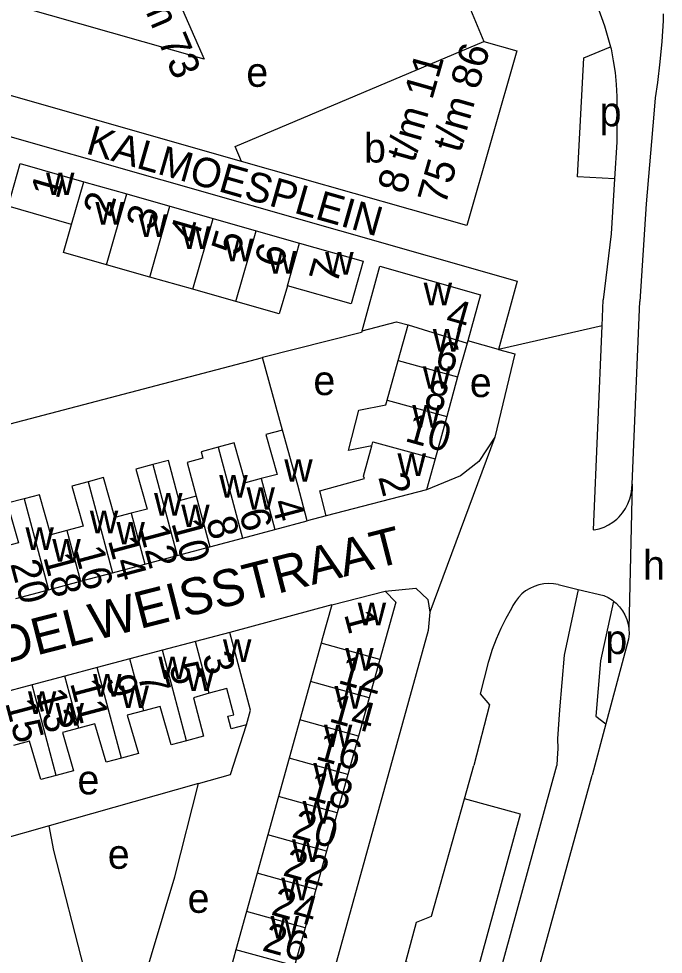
# Model space of a CAD drawing. Extents: x 161258 to 163262, y 380749 to 382054.
# Drawn here: x 163054.8 to 163142.3, y 381090.7 to 381217.9 of the extents above; entities that cross this region are included whole.
import ezdxf

# ---------------------------------------------------------------- set-up
doc = ezdxf.new("R2010")
doc.units = 0
for name, color, linetype in [('BLT_Basislijn', 7, 'Continuous'), ('BLT_Bebouwing', 7, 'Continuous'), ('BLT_Centroide', 7, 'Continuous'), ('BLT_Huisnummer', 7, 'Continuous'), ('BLT_Huisnummer_ tussenligend', 7, 'Continuous'), ('BLT_Huisnummer_reeks', 7, 'Continuous'), ('BLT_Onderverdeling_panden', 7, 'Continuous'), ('BLT_Straatnaam', 7, 'Continuous'), ('BLT_Straatnaam_verkleind', 7, 'Continuous'), ('BLT_Vlakafsluiter', 7, 'Continuous')]:
    doc.layers.add(name, color=color, linetype=linetype)

msp = doc.modelspace()

# ---------------------------------------------------------------- linework, layer by layer
at = {"layer": 'BLT_Basislijn'}
for p, q in [((163113.62, 381225.09), (163117.96, 381214.78)), ((163141.24, 381207.1), (163141.05, 381204.87)), ((163136, 381205.08), (163136.04, 381201.07)), ((163141.05, 381204.87), (163140, 381192.69)), ((163136.04, 381201.07), (163135.71, 381196.09)), ((163140, 381192.69), (163139.16, 381179.42)), ((163134.02, 381176.13), (163134.17, 381179.63)), ((163138.1, 381154.57), (163139.16, 381179.42)), ((163132.84, 381148.39), (163134.02, 381176.13)), ((163090.58, 381161.94), (163087.88, 381171.79)), ((163096.54, 381150.3), (163093.96, 381149.62)), ((163128.07, 381140.95), (163130.78, 381140.29)), ((163130.78, 381140.29), (163134.26, 381139.44)), ((163097.29, 381138.17), (163083.45, 381134.41)), ((163137.62, 381133.52), (163134.54, 381122.01)), ((163133.17, 381123.03), (163134.54, 381122.01)), ((163134.54, 381122.01), (163132.67, 381115.03)), ((163114.72, 381068.34), (163127.85, 381116.36)), ((163120.56, 381071.17), (163132.67, 381115.03)), ((163079.2, 381113.89), (163058.89, 381108.13)), ((163058.89, 381108.13), (163047.26, 381104.82))]:
    msp.add_line(p, q, dxfattribs=at)
for points in [[(163131.18, 381225.72), (163134.36, 381216.92), (163135.16, 381214.06)], [(163142.33, 381218.55), (163142.3, 381217.57), (163142.13, 381214.78), (163141.88, 381211.99), (163141.55, 381209.21), (163141.24, 381207.1)], [(163135.71, 381196.09), (163130.69, 381196.39), (163131.52, 381212.56), (163135.16, 381214.06)], [(163135.16, 381214.06), (163135.23, 381213.77), (163135.54, 381212.16), (163135.78, 381210.54), (163135.94, 381208.91), (163136.02, 381207.28), (163136.02, 381205.64), (163136, 381205.08)], [(163085.04, 381198.47), (163051.49, 381208.03)], [(163050.01, 381202.84), (163122.5, 381182.17), (163119.93, 381172.92)], [(163135.71, 381196.09), (163135.23, 381188.62), (163134.17, 381179.63)], [(163101.42, 381175.42), (163101.34, 381175.22), (163087.88, 381171.79)], [(163119.93, 381172.92), (163115.77, 381174.09)], [(163119.93, 381172.92), (163122.14, 381172.29), (163119.45, 381161)], [(163030.95, 381156.84), (163087.04, 381171.57), (163087.88, 381171.79)], [(163119.45, 381161), (163117.26, 381157.68), (163114.77, 381155.73), (163110.15, 381153.83)], [(163136.34, 381150.14), (163136.8, 381150.69), (163137.2, 381151.28), (163137.53, 381151.91), (163137.79, 381152.58), (163137.97, 381153.27), (163138.08, 381153.98), (163138.1, 381154.57)], [(163132.84, 381148.39), (163132.95, 381148.4), (163133.63, 381148.54), (163134.28, 381148.76), (163134.91, 381149.06), (163135.49, 381149.42), (163136.03, 381149.85), (163136.34, 381150.14)], [(163128.07, 381140.95), (163127.41, 381141.06), (163126.75, 381141.09), (163126.08, 381141.04), (163125.43, 381140.91), (163124.8, 381140.7), (163124.19, 381140.42), (163123.63, 381140.07), (163123.11, 381139.66), (163122.64, 381139.18), (163122.23, 381138.65), (163121.89, 381138.08), (163121.71, 381137.68)], [(163104.54, 381140.04), (163108.71, 381140.47), (163110.32, 381138.92), (163110.62, 381137.19)], [(163130.78, 381140.29), (163128.86, 381131.32), (163128.23, 381123.89), (163127.96, 381119.98)], [(163134.26, 381139.44), (163134.85, 381139.16), (163135.41, 381138.81), (163135.55, 381138.7)], [(163135.55, 381138.7), (163133.82, 381130.58), (163133.17, 381123.03)], [(163135.55, 381138.7), (163135.93, 381138.39), (163136.38, 381137.91), (163136.78, 381137.39), (163137.11, 381136.81), (163137.37, 381136.21), (163137.55, 381135.57), (163137.65, 381134.96)], [(163110.62, 381137.19), (163110.39, 381134.68), (163080.48, 381026.69), (163079.84, 381025.13)], [(163121.71, 381137.68), (163120.94, 381136.33), (163120.25, 381134.96), (163119.63, 381133.54), (163119.08, 381132.1), (163118.61, 381130.63), (163118.52, 381130.33)], [(163137.65, 381134.96), (163137.68, 381134.26), (163137.62, 381133.52)], [(163118.52, 381130.33), (163117.46, 381126.09), (163118.7, 381124.59), (163116.58, 381116.36)], [(163079.2, 381113.89), (163083.53, 381115.12), (163085.7, 381121.87)], [(163127.96, 381119.98), (163127.99, 381118.64), (163127.93, 381117.3), (163127.85, 381116.36)], [(163115.3, 381111.81), (163116.58, 381116.36)], [(163068.17, 381075.15), (163075.95, 381101.21), (163079.2, 381113.89)], [(163107.33, 381089.63), (163116.73, 381087.06), (163122.92, 381109.73), (163115.3, 381111.81)], [(163107.33, 381089.63), (163108.8, 381095.05), (163110.83, 381095.84), (163115.3, 381111.81)], [(163068.17, 381075.15), (163067.26, 381076.29), (163063.65, 381088.73), (163059.53, 381104.77), (163058.89, 381108.13)]]:
    msp.add_lwpolyline(points, dxfattribs=at)
at = {"layer": 'BLT_Bebouwing'}
for p, q in [((163063.59, 381195.71), (163069.45, 381194.04)), ((163069.45, 381194.04), (163075.3, 381192.37)), ((163075.3, 381192.37), (163081.16, 381190.7)), ((163081.16, 381190.7), (163087.02, 381189.03)), ((163087.02, 381189.03), (163092.9, 381187.35)), ((163072.56, 381182.75), (163066.7, 381184.42)), ((163078.42, 381181.08), (163072.56, 381182.75)), ((163084.27, 381179.41), (163078.42, 381181.08)), ((163106.31, 381171.41), (163107.65, 381176.24)), ((163115.68, 381173.77), (163114.39, 381169.19)), ((163104.81, 381166), (163106.31, 381171.41)), ((163114.39, 381169.19), (163112.9, 381163.78)), ((163112.9, 381163.78), (163111.32, 381158.03)), ((163077.63, 381157.54), (163078.86, 381152.95)), ((163111.32, 381158.03), (163110.15, 381153.83)), ((163110.15, 381153.83), (163096.54, 381150.3)), ((163089.55, 381148.44), (163093.96, 381149.62)), ((163085.16, 381147.27), (163089.55, 381148.44)), ((163080.7, 381146.08), (163085.16, 381147.27)), ((163076.27, 381144.89), (163080.7, 381146.08)), ((163071.87, 381143.71), (163076.27, 381144.89)), ((163067.51, 381142.55), (163071.87, 381143.71)), ((163063.16, 381141.38), (163067.51, 381142.55)), ((163058.78, 381140.21), (163063.16, 381141.38)), ((163054.38, 381139.04), (163058.78, 381140.21)), ((163097.29, 381138.17), (163104.54, 381140.04)), ((163083.45, 381134.41), (163078.76, 381133.19)), ((163078.76, 381133.19), (163074.3, 381132.01)), ((163074.3, 381132.01), (163069.86, 381130.83)), ((163095.84, 381132.98), (163094.4, 381127.77)), ((163069.86, 381130.83), (163065.43, 381129.65)), ((163103.82, 381130.76), (163102.38, 381125.55)), ((163065.43, 381129.65), (163061.03, 381128.48)), ((163061.03, 381128.48), (163056.59, 381127.3)), ((163056.59, 381127.3), (163052.14, 381126.12)), ((163094.4, 381127.77), (163092.95, 381122.56)), ((163102.38, 381125.55), (163100.93, 381120.34)), ((163092.95, 381122.56), (163091.5, 381117.35)), ((163100.93, 381120.34), (163099.48, 381115.13)), ((163091.5, 381117.35), (163090.05, 381112.14)), ((163099.48, 381115.13), (163098.03, 381109.92)), ((163090.05, 381112.14), (163088.61, 381106.93)), ((163098.03, 381109.92), (163096.59, 381104.71)), ((163088.61, 381106.93), (163087.16, 381101.72)), ((163096.59, 381104.71), (163095.14, 381099.5)), ((163087.16, 381101.72), (163085.71, 381096.51)), ((163095.14, 381099.5), (163093.69, 381094.29)), ((163085.71, 381096.51), (163084.26, 381091.3)), ((163093.69, 381094.29), (163092.24, 381089.09)), ((163084.26, 381091.3), (163082.81, 381086.09))]:
    msp.add_line(p, q, dxfattribs=at)
for points in [[(163113.62, 381225.09), (163101.88, 381220.16), (163097.21, 381231.22), (163075.7, 381222.13), (163079.94, 381212.35), (163054.77, 381219.52)], [(163085.04, 381198.47), (163084.14, 381200.48), (163117.96, 381214.78)], [(163117.96, 381214.78), (163122.43, 381213.51), (163115.65, 381189.74), (163085.04, 381198.47)], [(163061.93, 381189.89), (163053.3, 381192.4), (163054.94, 381198.18), (163063.59, 381195.71)], [(163066.7, 381184.42), (163060.85, 381186.09), (163061.93, 381189.89)], [(163092.9, 381187.35), (163101.55, 381184.89), (163099.9, 381179.11), (163091.25, 381181.57)], [(163101.42, 381175.42), (163103.84, 381184.23), (163117.51, 381180.32), (163115.77, 381174.09)], [(163091.25, 381181.57), (163090.15, 381177.73), (163084.27, 381179.41)], [(163101.42, 381175.42), (163106.09, 381176.67), (163107.65, 381176.24)], [(163115.77, 381174.09), (163115.68, 381173.77)], [(163102.73, 381159.79), (163099.54, 381159.17), (163100.95, 381164.64), (163104.64, 381165.36), (163104.81, 381166)], [(163090.58, 381161.94), (163088.32, 381161.34), (163089.86, 381155.92), (163087.71, 381155.34)], [(163093.96, 381149.62), (163092.67, 381154.45), (163090.58, 381161.94)], [(163087.71, 381155.34), (163085.55, 381154.76), (163084.02, 381160.2), (163081.85, 381159.62)], [(163096.54, 381150.3), (163095.65, 381153.67), (163101.75, 381155.35), (163101.58, 381155.66), (163102.73, 381159.79)], [(163081.85, 381159.62), (163079.53, 381159), (163079.77, 381158.11), (163077.63, 381157.54)], [(163072.96, 381157.25), (163070.67, 381156.64), (163072.21, 381151.21), (163070.02, 381150.63)], [(163078.86, 381152.95), (163076.56, 381152.34), (163075.09, 381157.82), (163072.96, 381157.25)], [(163064.2, 381154.92), (163061.96, 381154.32), (163063.5, 381148.88), (163061.31, 381148.29)], [(163070.02, 381150.63), (163067.83, 381150.04), (163066.29, 381155.48), (163064.2, 381154.92)], [(163055.47, 381152.6), (163053.2, 381151.99), (163054.73, 381146.6), (163052.52, 381146.01)], [(163061.31, 381148.29), (163059.12, 381147.71), (163057.58, 381153.16), (163055.47, 381152.6)], [(163104.54, 381140.04), (163105.99, 381138.56), (163103.82, 381130.76)], [(163097.29, 381138.17), (163095.95, 381133.36), (163095.84, 381132.98)], [(163085.7, 381121.87), (163086.25, 381123.85), (163083.45, 381134.41)], [(163085.7, 381121.87), (163083.61, 381121.32), (163083.15, 381123.03), (163083.96, 381123.25), (163083.02, 381126.8), (163080.63, 381126.16)], [(163080.63, 381126.16), (163078.48, 381125.56), (163079.87, 381120.32), (163077.56, 381119.71)], [(163077.56, 381119.71), (163075.48, 381119.15), (163073.97, 381124.38), (163071.73, 381123.79)], [(163071.73, 381123.79), (163069.5, 381123.19), (163071.01, 381117.96), (163068.7, 381117.34)], [(163068.7, 381117.34), (163066.61, 381116.79), (163065.11, 381122), (163062.91, 381121.42)], [(163062.91, 381121.42), (163060.71, 381120.83), (163062.21, 381115.61), (163059.86, 381114.99)], [(163059.86, 381114.99), (163057.74, 381114.42), (163056.23, 381119.63), (163054.02, 381119.05)]]:
    msp.add_lwpolyline(points, dxfattribs=at)
at = {"layer": 'BLT_Onderverdeling_panden'}
for p, q in [((163061.93, 381189.89), (163063.59, 381195.71)), ((163066.7, 381184.42), (163069.45, 381194.04)), ((163072.56, 381182.75), (163075.3, 381192.37)), ((163078.42, 381181.08), (163081.16, 381190.7)), ((163084.27, 381179.41), (163087.02, 381189.03)), ((163091.25, 381181.57), (163092.9, 381187.35)), ((163107.65, 381176.24), (163115.68, 381173.77)), ((163106.31, 381171.41), (163114.39, 381169.19)), ((163104.81, 381166), (163112.9, 381163.78)), ((163081.85, 381159.62), (163085.16, 381147.27)), ((163072.96, 381157.25), (163076.27, 381144.89)), ((163064.2, 381154.92), (163067.51, 381142.55)), ((163087.71, 381155.34), (163089.55, 381148.44)), ((163055.47, 381152.6), (163058.78, 381140.21)), ((163078.86, 381152.95), (163080.7, 381146.08)), ((163070.02, 381150.63), (163071.87, 381143.71)), ((163061.31, 381148.29), (163063.16, 381141.38)), ((163080.63, 381126.16), (163078.76, 381133.19)), ((163077.56, 381119.71), (163074.3, 381132.01)), ((163103.82, 381130.76), (163095.84, 381132.98)), ((163071.73, 381123.79), (163069.86, 381130.83)), ((163068.7, 381117.34), (163065.43, 381129.65)), ((163062.91, 381121.42), (163061.03, 381128.48)), ((163059.86, 381114.99), (163056.59, 381127.3)), ((163102.38, 381125.55), (163094.4, 381127.77)), ((163100.93, 381120.34), (163092.95, 381122.56)), ((163099.48, 381115.13), (163091.5, 381117.35)), ((163098.03, 381109.92), (163090.05, 381112.14)), ((163096.59, 381104.71), (163088.61, 381106.93)), ((163095.14, 381099.5), (163087.16, 381101.72)), ((163093.69, 381094.29), (163085.71, 381096.51)), ((163092.24, 381089.09), (163084.26, 381091.3))]:
    msp.add_line(p, q, dxfattribs=at)
msp.add_lwpolyline([(163102.73, 381159.79), (163102.88, 381160.35), (163111.32, 381158.03)], dxfattribs=at)
at = {"layer": 'BLT_Vlakafsluiter'}
for p, q in [((163134.02, 381176.13), (163119.93, 381172.92)), ((163119.45, 381161), (163110.62, 381137.19)), ((163138.1, 381154.57), (163137.65, 381134.96))]:
    msp.add_line(p, q, dxfattribs=at)

# ---------------------------------------------------------------- texts
at = {"layer": 'BLT_Centroide'}
for s, p in [('e', (163085.68, 381208.61)), ('p', (163133.68, 381203.24)), ('b', (163101.67, 381198.32)), ('w', (163058.46, 381193.88)), ('w', (163065.17, 381189.89)), ('w', (163071.03, 381188.2)), ('w', (163076.89, 381186.55)), ('w', (163082.73, 381184.88)), ('w', (163088.59, 381183.2)), ('w', (163096.39, 381183.06)), ('w', (163109.77, 381178.91)), ('w', (163111.01, 381172.62)), ('w', (163109.64, 381167.56)), ('e', (163094.79, 381166.7)), ('e', (163116.04, 381166.43)), ('w', (163108.22, 381162.28)), ('w', (163106.22, 381155.69)), ('w', (163090.83, 381154.91)), ('w', (163082, 381152.75)), ('w', (163085.7, 381151.11)), ('w', (163073.14, 381150.31)), ('w', (163064.41, 381147.92)), ('w', (163076.83, 381148.75)), ('w', (163055.66, 381145.66)), ('w', (163068.03, 381146.39)), ('w', (163059.31, 381144.05)), ('h', (163139.58, 381141.59)), ('w', (163100.81, 381135.41)), ('p', (163134.46, 381131.49)), ('w', (163082.5, 381130.41)), ('w', (163099.11, 381129.25)), ('w', (163073.72, 381128.08)), ('w', (163077.47, 381126.47)), ('w', (163064.86, 381125.72)), ('w', (163068.58, 381124.14)), ('w', (163097.66, 381124.06)), ('w', (163056, 381123.36)), ('w', (163059.75, 381121.78)), ('w', (163096.22, 381118.84)), ('w', (163094.77, 381113.62)), ('e', (163062.73, 381112.42)), ('w', (163093.32, 381108.44)), ('e', (163066.85, 381102.3)), ('w', (163091.88, 381103.22)), ('w', (163090.42, 381098)), ('e', (163077.7, 381096.31)), ('w', (163088.97, 381092.81))]:
    msp.add_text(s, height=4, dxfattribs=at).set_placement(p)
at = {"layer": 'BLT_Huisnummer'}
for s, rotation, p in [('1', 73.8697, (163060.13, 381193.21)), ('2', 73.8697, (163067.25, 381190.73)), ('3', 73.8697, (163073.08, 381188.98)), ('4', 73.8697, (163078.97, 381187.19)), ('5', 73.8697, (163084.66, 381185.53)), ('6', 73.8697, (163090.51, 381183.77)), ('7', 74.0827, (163097.96, 381181.62)), ('4', 344.094, (163112.56, 381176.08)), ('6', 344.5187, (163111.11, 381170.43)), ('10', 344.5187, (163107.08, 381160.48)), ('2', 284.4944, (163103.58, 381155.57)), ('4', 284.9783, (163089.04, 381152.11)), ('8', 284.9838, (163080.17, 381149.66)), ('12', 284.9887, (163071.07, 381148.58)), ('16', 284.9748, (163062.28, 381145.65)), ('20', 284.9795, (163053.58, 381143.77)), ('1', 284.8701, (163098.94, 381136.91)), ('3', 284.8788, (163079.66, 381131.28)), ('12', 344.4689, (163097.98, 381127.57)), ('7', 284.8861, (163070.88, 381128.6)), ('11', 284.8744, (163061.7, 381127.56)), ('15', 284.8711, (163052.88, 381124.87)), ('16', 344.467, (163094.95, 381117.23)), ('20', 344.467, (163091.69, 381106.65)), ('24', 344.467, (163088.89, 381096.09))]:
    msp.add_text(s, height=4, rotation=rotation, dxfattribs=at).set_placement(p)
at = {"layer": 'BLT_Huisnummer_ tussenligend'}
for s, rotation, p in [('8', 344.5187, (163109.62, 381165.11)), ('6', 284.9783, (163084.67, 381150.75)), ('10', 284.9838, (163075.47, 381149.31)), ('14', 284.9887, (163066.84, 381146.96)), ('18', 284.9748, (163058.06, 381144.69)), ('5', 284.8788, (163075.15, 381129.89)), ('9', 284.8861, (163066.54, 381128.13)), ('13', 284.8744, (163057.07, 381126.26)), ('14', 344.4689, (163096.75, 381122.36)), ('18', 344.467, (163093.74, 381111.84)), ('22', 344.467, (163090.49, 381101.43)), ('26', 344.467, (163087.68, 381091.23))]:
    msp.add_text(s, height=4, rotation=rotation, dxfattribs=at).set_placement(p)
at = {"layer": 'BLT_Huisnummer_reeks'}
for s, rotation, p in [('58 t/m 73', 292.8419, (163067.29, 381229.93)), ('75 t/m 86', 74.0826, (163112.71, 381192.37)), ('8 t/m 11', 74.0826, (163107.26, 381193.87))]:
    msp.add_text(s, height=4, rotation=rotation, dxfattribs=at).set_placement(p)
at = {"layer": 'BLT_Straatnaam'}
msp.add_text('EDELWEISSTRAAT', height=5, rotation=14.3454, dxfattribs=at).set_placement((163048.17, 381128.99))
at = {"layer": 'BLT_Straatnaam_verkleind'}
msp.add_text('KALMOESPLEIN', height=4, rotation=344.0832, dxfattribs=at).set_placement((163063.72, 381199.59))

doc.saveas('drawing.dxf')
